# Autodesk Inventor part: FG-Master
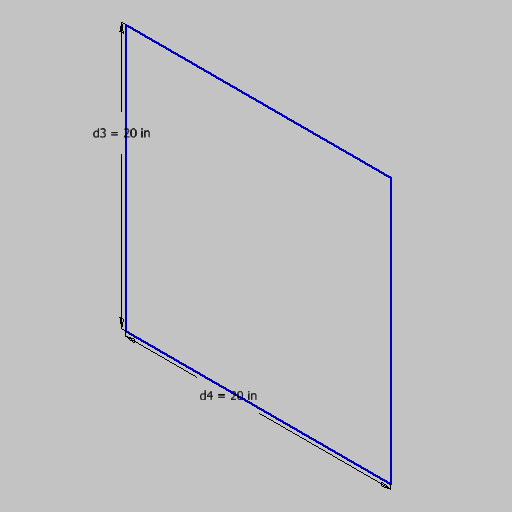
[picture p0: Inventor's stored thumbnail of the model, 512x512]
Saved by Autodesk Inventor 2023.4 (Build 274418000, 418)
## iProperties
Created: 2023-10
Part Number: FG-Master
Material: 10GA CRS
Document SubType Name: Sheet Metal
Designer: Fred L.
Density: 7.86 g/cm^3
Sheet Metal Rule: 10 ga
Appearance: Metal-Steel
Quantity: 0
Mass: 0
SurfaceArea: 0
Author: Fred L.
Revision Number: 00
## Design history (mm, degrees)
sketch "Sketch3"
  geometry: L1 (0, 0)-(508, 0); L2 (508, 0)-(508, 508); L3 (508, 508)-(0, 508); L4 (0, 508)-(0, 0)
  constraints: 8 end point, 2 parallel, 1 horizontal, 1 perpendicular
  dimensions: "d3" = 508 distance of L3.end L1.start; "d4" = 508 distance of L1.start L1.end
body "Solid1"
other parameters: "Thickness" = 3.429 (derived), "KFactor" = 4.4, "BendRadius" = 3.429 (= Thickness), "BendReliefWidth" = 1.7145 (= 0.5 x Thickness), "BendReliefDepth" = 1.7145 (= 0.5 x Thickness), "CornerReliefSize" = 13.716 (= 4 x Thickness), "SeamGap" = 0.00508, "MinimumRemnant" = 6.858 (= 2 x Thickness), "TransitionRadius" = 3.429 (= BendRadius), "JacobiRadiusSize" = 3.429 (= BendRadius), "GapSize" = 0.254 (derived), "alga10" = 2.5908 [user parameter], "alga11" = 2.3114 [user parameter], "alga12" = 2.0574 [user parameter], "alga14" = 1.6256 [user parameter], "alga16" = 1.2954 [user parameter], "alga18" = 1.016 [user parameter], "alga20" = 0.8128 [user parameter], "alga22" = 0.635 [user parameter], "alga24" = 0.508 [user parameter], "ga9" = 3.6576 [user parameter], "ga10" = 3.4036 [user parameter], "ga11" = 3.0226 [user parameter], "ga12" = 2.65684 [user parameter], "ga14" = 1.89738 [user parameter], "ga16" = 1.51892 [user parameter], "ga18" = 1.21412 [user parameter], "ga20" = 0.91186 [user parameter], "ga22" = 0.75946 [user parameter], "ga24" = 0.60706 [user parameter], "gvga12" = 2.75336 [user parameter], "gvga14" = 1.9939 [user parameter], "gvga16" = 1.6129 [user parameter], "gvga18" = 1.31064 [user parameter], "gvga20" = 1.00584 [user parameter], "gvga22" = 0.85344 [user parameter], "gvga24" = 0.70104 [user parameter], "ssga10" = 3.57124 [user parameter], "ssga11" = 3.175 [user parameter], "ssga12" = 2.7686 [user parameter], "ssga14" = 1.98374 [user parameter], "ssga16" = 1.5875 [user parameter], "ssga18" = 1.27 [user parameter], "ssga20" = 0.9398 [user parameter], "ssga22" = 0.7874 [user parameter], "ssga24" = 0.635 [user parameter], "Length" = 0 [user parameter; used in 1 equation term], "Width" = 0 [user parameter; used in 1 equation term], "Area" = 0 (computed from Length, Width) [user parameter]
